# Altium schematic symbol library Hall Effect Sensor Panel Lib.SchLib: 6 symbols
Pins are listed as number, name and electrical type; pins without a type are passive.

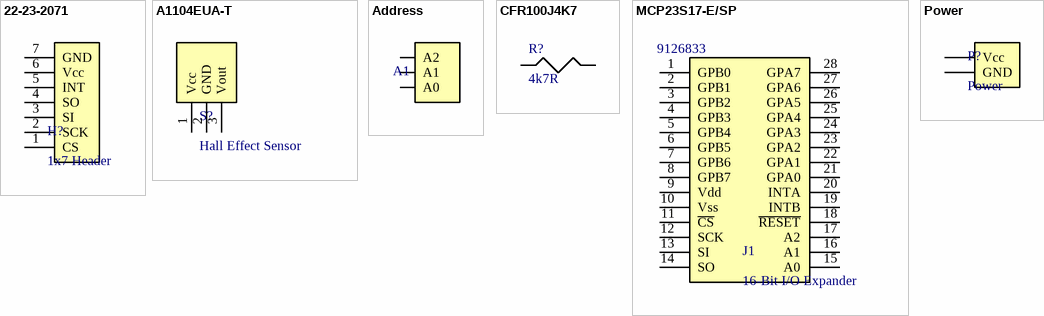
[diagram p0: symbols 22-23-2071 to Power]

## 22-23-2071
designator H?, comment 1x7 Header
CONN HEADER VERT 7POS 2.54MM; Manufacturer: Molex; Number of Contacts: 7; Contact Resistance: 10mR; Gender: Male; Max Voltage Rating (AC): 250V; Current Rating: 4A; Max Current Rating: 10A; Insulation Resistance: 500GR; Approvals: UL,CSA; Glow Wire Compliant: Non-compliant
footprint Molex
pins: 1 CS, 2 SCK, 3 SI, 4 SO, 5 INT, 6 Vcc, 7 GND

## A1104EUA-T
designator S?, comment Hall Effect Sensor
ALLEGRO MICROSYSTEMS - A1104EUA-T - IC, HALL-EFFECT SWITCH SIP-3; Output Current: 25mA; Max Supply Current: 7.5mA; Min Supply Voltage: 3.8V; Max Supply Voltage: 24V; Output Type: Digital
footprint A1104EUA-T
pins: 1 Vcc, 2 GND, 3 Vout

## Address
designator A1
footprint Address
pins: 1 A0, 2 A1, 3 A2

## CFR100J4K7
designator R?, comment 4k7R
TE CONNECTIVITY         CFR100J4K7             Through Hole Resistor, 4.7 kohm, 500 V, Axial Leaded, 1 W,  5%, CFR Series; Temperature Coefficient: 0ppm/°C; Resistance: 4.7kR; Power Rating: 1W; Number of Resistors: 1; Voltage Rating: 500V
footprint CFR100J4K7
pins: 1, 2

## MCP23S17-E/SP
designator J1, comment 16-Bit I/O Expander  Supplier Part Number 1: 9126833
TE CONNECTIVITY         CFR100J4K7             Through Hole Resistor, 4.7 kohm, 500 V, Axial Leaded, 1 W,  5%, CFR Series; Manufacturer: Microchip; Manufacturer Part Number: MCP23S17-E/SP; Description: MICROCHIP - MCP23S17-E/SP - IC, 16BIT I/O EXPANDER, SPI, 23S17; Interface: SPI,Serial; Nominal Supply Current: 1mA; Number of Channels: 1; Min Supply Voltage: 1.8V; Max Supply Voltage: 5.5V; Number of I/Os: 16; Frequency: 10MHz; Temperature Coefficient: 0ppm/°C; Resistance: 4.7kR; Power Rating: 1W; Voltage Rating: 500V
footprint MCP23S17-E/SP
pins: 1 GPB0, 2 GPB1, 3 GPB2, 4 GPB3, 5 GPB4, 6 GPB5, 7 GPB6, 8 GPB7, 9 Vdd, 10 Vss, 11 ~{CS}, 12 SCK, 13 SI, 14 SO, 15 A0, 16 A1, 17 A2, 18 ~{RESET}, 19 INTB, 20 INTA, 21 GPA0, 22 GPA1, 23 GPA2, 24 GPA3, 25 GPA4, 26 GPA5, 27 GPA6, 28 GPA7

## Power
designator P?
footprint Power
pins: 1 Vcc, 2 GND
